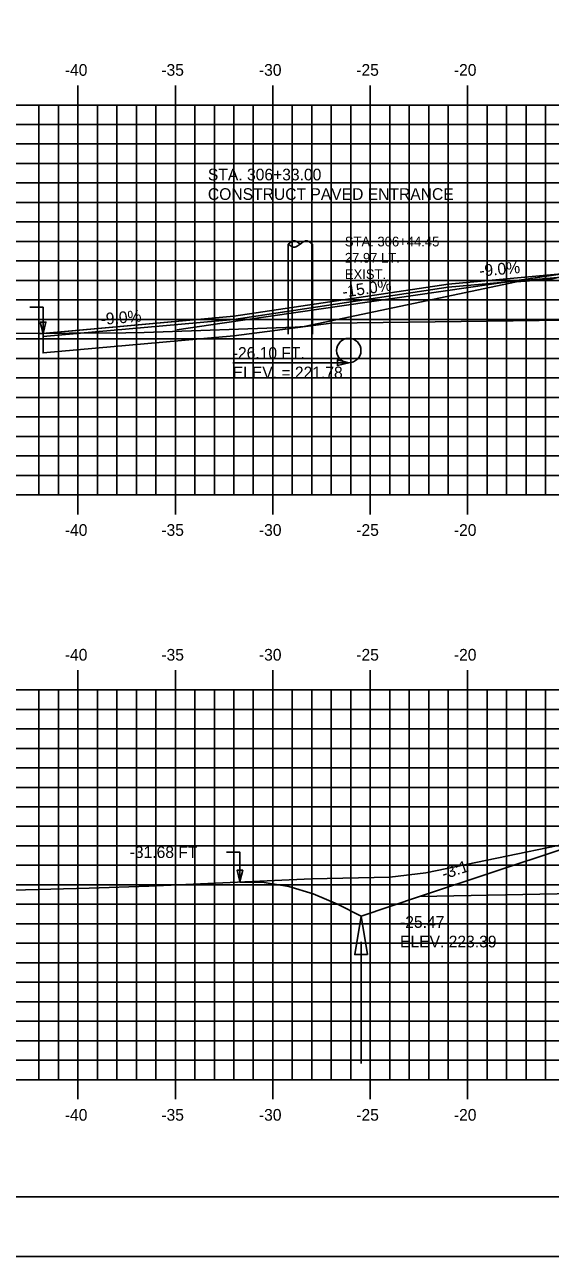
# Model space of a CAD drawing. Extents: x 1137433 to 1137603, y 608981 to 609091.
# Drawn here: x 1137472.9 to 1137499.9, y 608981.3 to 609044.5 of the extents above; entities that cross this region are included whole.
import ezdxf

# ---------------------------------------------------------------- set-up
doc = ezdxf.new("R2010")
doc.units = 0
for name, color, linetype in [('ANNOTATION', 7, 'Continuous'), ('BORDER', 7, 'Continuous'), ('D_Drainage_Culvert', 7, 'Continuous'), ('D_Drainage_Ditch_Line', 7, 'Continuous'), ('D_Roadway_Edge_Shoulder', 7, 'Continuous'), ('D_Roadway_SlopeLines', 7, 'Continuous'), ('D_Roadway_SubGrade', 7, 'Continuous'), ('D_Text_Monospaced', 7, 'Continuous'), ('D_Text_Standard', 7, 'Continuous'), ('H_V ANNOTATION', 7, 'Continuous'), ('MAJOR', 7, 'Continuous'), ('MINOR', 7, 'Continuous'), ('PATTERNING', 7, 'Continuous'), ('PLOT BOUNDARY', 7, 'Continuous'), ('S_Roadway_Centerline', 7, 'Continuous'), ('S_Utilities_Pole_Power', 7, 'Continuous')]:
    doc.layers.add(name, color=color, linetype=linetype)

msp = doc.modelspace()

# ---------------------------------------------------------------- linework, layer by layer
for points in [[(1137480.733, 609028.805), (1137483.056, 609029.142), (1137500.653, 609031.693), (1137501.13, 609031.716), (1137504.653, 609031.88), (1137505.953, 609031.941), (1137515.653, 609032.393), (1137516.953, 609032.453), (1137526.653, 609032.905), (1137527.13, 609032.89), (1137530.653, 609032.772), (1137537.514, 609030.485), (1137538.461, 609030.169)], [(1137483.968, 609000.475), (1137485.218, 609000.445), (1137486.468, 609000.245), (1137487.718, 608999.875), (1137488.968, 608999.335), (1137490.184, 608998.727), (1137493.184, 608999.727), (1137500.652, 609002.217), (1137500.653, 609002.217), (1137504.653, 609002.457), (1137515.653, 609003.117), (1137526.653, 609003.777), (1137530.966, 609003.69), (1137533.053, 609003.002), (1137534.745, 609002.444), (1137536.143, 609001.984), (1137537.258, 609001.616), (1137538.984, 609001.048)]]:
    msp.add_lwpolyline(points)
at = {"layer": 'BORDER'}
msp.add_lwpolyline([(1137440.653, 608984.335), (1137600.653, 608984.335), (1137600.653, 609089.335), (1137440.653, 609089.335)], close=True, dxfattribs=at)
at = {"layer": 'D_Drainage_Culvert'}
msp.add_circle((1137489.553, 609027.74), 0.625, dxfattribs=at)
at = {"layer": 'D_Drainage_Ditch_Line'}
msp.add_line((1137490.184, 608997.415), (1137490.183, 608991.171), dxfattribs=at)
msp.add_lwpolyline([(1137490.512, 608996.759), (1137489.856, 608996.759), (1137490.184, 608998.727)], close=True, dxfattribs=at)
at = {"layer": 'D_Roadway_Edge_Shoulder'}
msp.add_lwpolyline([(1137473.862, 609028.455), (1137483.653, 609029.337), (1137494.653, 609030.987), (1137500.653, 609031.527)], dxfattribs=at)
at = {"layer": 'D_Roadway_SlopeLines'}
for points in [[(1137490.184, 608998.727), (1137488.968, 608999.335), (1137487.718, 608999.875), (1137486.468, 609000.245), (1137485.218, 609000.445), (1137483.968, 609000.475)], [(1137493.184, 608999.727), (1137490.184, 608998.727)]]:
    msp.add_lwpolyline(points, dxfattribs=at)
at = {"layer": 'D_Roadway_SubGrade'}
for p, q in [((1137500.653, 609031.693), (1137494.653, 609031.153)), ((1137483.653, 609029.503), (1137494.653, 609031.153)), ((1137483.653, 609029.503), (1137473.862, 609028.622)), ((1137488.653, 609029.141), (1137500.653, 609029.3)), ((1137488.653, 609029.141), (1137500.653, 609029.3)), ((1137473.862, 609028.622), (1137473.862, 609028.455))]:
    msp.add_line(p, q, dxfattribs=at)
msp.add_lwpolyline([(1137473.862, 609028.622), (1137473.862, 609027.622), (1137483.653, 609028.503), (1137488.653, 609029.141)], dxfattribs=at)
msp.add_lwpolyline([(1137504.653, 609002.04), (1137504.653, 609002.207), (1137500.653, 609001.967), (1137500.653, 609002.217), (1137500.652, 609002.217), (1137493.184, 608999.727), (1137504.653, 608999.957)], close=True, dxfattribs=at)
at = {"layer": 'D_Text_Standard'}
msp.add_line((1137483.598, 609027.115), (1137487.98, 609027.115), dxfattribs=at)
for points in [[(1137473.862, 609028.622), (1137473.86, 609029.96), (1137473.18, 609029.96)], [(1137489.553, 609027.115), (1137488.66, 609027.115), (1137487.98, 609027.115)], [(1137483.97, 609000.502), (1137483.961, 609002.011), (1137483.281, 609002.011)]]:
    msp.add_lwpolyline(points, dxfattribs=at)
for points in [[(1137473.862, 609028.622), (1137473.716, 609029.204), (1137474.007, 609029.204)], [(1137489.553, 609027.115), (1137488.971, 609026.97), (1137488.971, 609027.261)], [(1137483.97, 609000.502), (1137483.821, 609001.083), (1137484.112, 609001.085)]]:
    msp.add_lwpolyline(points, close=True, dxfattribs=at)
at = {"layer": 'MAJOR'}
for p, q in [((1137475.653, 609041.337), (1137475.653, 609040.335)), ((1137480.653, 609041.337), (1137480.653, 609040.335)), ((1137485.653, 609041.337), (1137485.653, 609040.335)), ((1137490.653, 609041.337), (1137490.653, 609040.335)), ((1137495.653, 609041.337), (1137495.653, 609040.335)), ((1137445.653, 609040.335), (1137585.653, 609040.335)), ((1137445.653, 609040.335), (1137585.653, 609040.335)), ((1137475.653, 609020.335), (1137475.653, 609040.335)), ((1137480.653, 609020.335), (1137480.653, 609040.335)), ((1137485.653, 609020.335), (1137485.653, 609040.335)), ((1137490.653, 609020.335), (1137490.653, 609040.335)), ((1137495.653, 609020.335), (1137495.653, 609040.335)), ((1137445.653, 609035.335), (1137585.653, 609035.335)), ((1137445.653, 609030.335), (1137585.653, 609030.335)), ((1137445.653, 609025.335), (1137585.653, 609025.335)), ((1137445.653, 609020.335), (1137585.653, 609020.335)), ((1137445.653, 609020.335), (1137585.653, 609020.335)), ((1137475.653, 609019.333), (1137475.653, 609020.335)), ((1137480.653, 609019.333), (1137480.653, 609020.335)), ((1137485.653, 609019.333), (1137485.653, 609020.335)), ((1137490.653, 609019.333), (1137490.653, 609020.335)), ((1137495.653, 609019.333), (1137495.653, 609020.335)), ((1137475.653, 609011.337), (1137475.653, 609010.335)), ((1137480.653, 609011.337), (1137480.653, 609010.335)), ((1137485.653, 609011.337), (1137485.653, 609010.335)), ((1137490.653, 609011.337), (1137490.653, 609010.335)), ((1137495.653, 609011.337), (1137495.653, 609010.335)), ((1137445.653, 609010.335), (1137585.653, 609010.335)), ((1137445.653, 609010.335), (1137585.653, 609010.335)), ((1137475.653, 608990.335), (1137475.653, 609010.335)), ((1137480.653, 608990.335), (1137480.653, 609010.335)), ((1137485.653, 608990.335), (1137485.653, 609010.335)), ((1137490.653, 608990.335), (1137490.653, 609010.335)), ((1137495.653, 608990.335), (1137495.653, 609010.335)), ((1137445.653, 609005.335), (1137585.653, 609005.335)), ((1137445.653, 609000.335), (1137585.653, 609000.335)), ((1137445.653, 608995.335), (1137585.653, 608995.335)), ((1137445.653, 608990.335), (1137585.653, 608990.335)), ((1137445.653, 608990.335), (1137585.653, 608990.335)), ((1137475.653, 608989.333), (1137475.653, 608990.335)), ((1137480.653, 608989.333), (1137480.653, 608990.335)), ((1137485.653, 608989.333), (1137485.653, 608990.335)), ((1137490.653, 608989.333), (1137490.653, 608990.335)), ((1137495.653, 608989.333), (1137495.653, 608990.335))]:
    msp.add_line(p, q, dxfattribs=at)
at = {"layer": 'MINOR'}
for p, q in [((1137473.653, 609020.335), (1137473.653, 609040.335)), ((1137474.653, 609020.335), (1137474.653, 609040.335)), ((1137476.653, 609020.335), (1137476.653, 609040.335)), ((1137477.653, 609020.335), (1137477.653, 609040.335)), ((1137478.653, 609020.335), (1137478.653, 609040.335)), ((1137479.653, 609020.335), (1137479.653, 609040.335)), ((1137481.653, 609020.335), (1137481.653, 609040.335)), ((1137482.653, 609020.335), (1137482.653, 609040.335)), ((1137483.653, 609020.335), (1137483.653, 609040.335)), ((1137484.653, 609020.335), (1137484.653, 609040.335)), ((1137486.653, 609020.335), (1137486.653, 609040.335)), ((1137487.653, 609020.335), (1137487.653, 609040.335)), ((1137488.653, 609020.335), (1137488.653, 609040.335)), ((1137489.653, 609020.335), (1137489.653, 609040.335)), ((1137491.653, 609020.335), (1137491.653, 609040.335)), ((1137492.653, 609020.335), (1137492.653, 609040.335)), ((1137493.653, 609020.335), (1137493.653, 609040.335)), ((1137494.653, 609020.335), (1137494.653, 609040.335)), ((1137496.653, 609020.335), (1137496.653, 609040.335)), ((1137497.653, 609020.335), (1137497.653, 609040.335)), ((1137498.653, 609020.335), (1137498.653, 609040.335)), ((1137499.653, 609020.335), (1137499.653, 609040.335)), ((1137445.653, 609039.335), (1137585.653, 609039.335)), ((1137445.653, 609038.335), (1137585.653, 609038.335)), ((1137445.653, 609037.335), (1137585.653, 609037.335)), ((1137445.653, 609036.335), (1137585.653, 609036.335)), ((1137445.653, 609034.335), (1137585.653, 609034.335)), ((1137445.653, 609033.335), (1137585.653, 609033.335)), ((1137445.653, 609032.335), (1137585.653, 609032.335)), ((1137445.653, 609031.335), (1137585.653, 609031.335)), ((1137445.653, 609029.335), (1137585.653, 609029.335)), ((1137445.653, 609028.335), (1137585.653, 609028.335)), ((1137445.653, 609027.335), (1137585.653, 609027.335)), ((1137445.653, 609026.335), (1137585.653, 609026.335)), ((1137445.653, 609024.335), (1137585.653, 609024.335)), ((1137445.653, 609023.335), (1137585.653, 609023.335)), ((1137445.653, 609022.335), (1137585.653, 609022.335)), ((1137445.653, 609021.335), (1137585.653, 609021.335)), ((1137473.653, 608990.335), (1137473.653, 609010.335)), ((1137474.653, 608990.335), (1137474.653, 609010.335)), ((1137476.653, 608990.335), (1137476.653, 609010.335)), ((1137477.653, 608990.335), (1137477.653, 609010.335)), ((1137478.653, 608990.335), (1137478.653, 609010.335)), ((1137479.653, 608990.335), (1137479.653, 609010.335)), ((1137481.653, 608990.335), (1137481.653, 609010.335)), ((1137482.653, 608990.335), (1137482.653, 609010.335)), ((1137483.653, 608990.335), (1137483.653, 609010.335)), ((1137484.653, 608990.335), (1137484.653, 609010.335)), ((1137486.653, 608990.335), (1137486.653, 609010.335)), ((1137487.653, 608990.335), (1137487.653, 609010.335)), ((1137488.653, 608990.335), (1137488.653, 609010.335)), ((1137489.653, 608990.335), (1137489.653, 609010.335)), ((1137491.653, 608990.335), (1137491.653, 609010.335)), ((1137492.653, 608990.335), (1137492.653, 609010.335)), ((1137493.653, 608990.335), (1137493.653, 609010.335)), ((1137494.653, 608990.335), (1137494.653, 609010.335)), ((1137496.653, 608990.335), (1137496.653, 609010.335)), ((1137497.653, 608990.335), (1137497.653, 609010.335)), ((1137498.653, 608990.335), (1137498.653, 609010.335)), ((1137499.653, 608990.335), (1137499.653, 609010.335)), ((1137445.653, 609009.335), (1137585.653, 609009.335)), ((1137445.653, 609008.335), (1137585.653, 609008.335)), ((1137445.653, 609007.335), (1137585.653, 609007.335)), ((1137445.653, 609006.335), (1137585.653, 609006.335)), ((1137445.653, 609004.335), (1137585.653, 609004.335)), ((1137445.653, 609003.335), (1137585.653, 609003.335)), ((1137445.653, 609002.335), (1137585.653, 609002.335)), ((1137445.653, 609001.335), (1137585.653, 609001.335)), ((1137445.653, 608999.335), (1137585.653, 608999.335)), ((1137445.653, 608998.335), (1137585.653, 608998.335)), ((1137445.653, 608997.335), (1137585.653, 608997.335)), ((1137445.653, 608996.335), (1137585.653, 608996.335)), ((1137445.653, 608994.335), (1137585.653, 608994.335)), ((1137445.653, 608993.335), (1137585.653, 608993.335)), ((1137445.653, 608992.335), (1137585.653, 608992.335)), ((1137445.653, 608991.335), (1137585.653, 608991.335))]:
    msp.add_line(p, q, dxfattribs=at)
at = {"layer": 'PATTERNING'}
msp.add_line((1137483.653, 609029.503), (1137473.653, 609028.603), dxfattribs=at)
at = {"layer": 'PLOT BOUNDARY'}
msp.add_lwpolyline([(1137432.56, 608981.276), (1137602.56, 608981.276), (1137602.56, 609091.276), (1137432.56, 609091.276)], close=True, dxfattribs=at)
at = {"layer": 'S_Roadway_Centerline'}
for points in [[(1137445.653, 609028.703), (1137460.066, 609028.556), (1137460.633, 609028.548), (1137478.111, 609028.646), (1137479.06, 609028.67), (1137486.804, 609028.946), (1137487.264, 609028.966), (1137498.159, 609031.27), (1137499.941, 609031.407), (1137500.381, 609031.497), (1137500.618, 609031.505), (1137510.823, 609031.631), (1137513.506, 609031.615), (1137521.857, 609031.577), (1137522.115, 609031.498), (1137522.315, 609031.418), (1137525.004, 609031.182), (1137525.888, 609031.035), (1137530.343, 609030.697), (1137531.057, 609030.727), (1137534.993, 609030.582), (1137537.95, 609030.665), (1137547.085, 609030.758)], [(1137445.653, 609000.068), (1137449.602, 608999.97), (1137450.522, 608999.958), (1137471.63, 609000.04), (1137476.229, 609000.162), (1137479.292, 609000.271), (1137487.646, 609000.636), (1137491.658, 609000.725), (1137493.508, 609000.954), (1137500.799, 609002.457), (1137507.803, 609002.706), (1137511.492, 609002.758), (1137515.564, 609002.741), (1137522.315, 609002.7), (1137524.764, 609002.536), (1137526.981, 609002.445), (1137539.217, 609001.937)]]:
    msp.add_lwpolyline(points, dxfattribs=at)
at = {"layer": 'S_Utilities_Pole_Power'}
for p, q in [((1137486.435, 609033.203), (1137486.591, 609033.314)), ((1137486.435, 609028.584), (1137486.438, 609033.203)), ((1137486.591, 609033.092), (1137486.435, 609033.203)), ((1137486.903, 609033.314), (1137487.06, 609033.203)), ((1137487.06, 609033.203), (1137486.903, 609033.092)), ((1137487.216, 609033.314), (1137487.06, 609033.203)), ((1137487.685, 609033.203), (1137487.529, 609033.314)), ((1137487.685, 609028.584), (1137487.688, 609033.203))]:
    msp.add_line(p, q, dxfattribs=at)
for centre, start, end in [((1137486.747, 609033.093), 90, 125.26439), ((1137486.747, 609033.314), 234.73561, 270), ((1137486.747, 609033.093), 54.73561, 90), ((1137486.747, 609033.314), 270, 305.26439), ((1137487.372, 609033.093), 90, 125.26439), ((1137487.372, 609033.093), 54.73561, 90)]:
    msp.add_arc(centre, 0.271, start, end, dxfattribs=at)

# ---------------------------------------------------------------- texts
at = {"layer": 'ANNOTATION'}
for s, p in [('STA. 306+33.00', (1137482.323, 609036.469)), ('CONSTRUCT PAVED ENTRANCE', (1137482.323, 609035.467))]:
    msp.add_text(s, height=0.6, dxfattribs=at).set_placement(p)
for s, rotation, p in [('-9.0%', 5.05846, (1137496.277, 609031.535)), ('-15.0%', 8.25039, (1137489.263, 609030.452)), ('-9.0%', 5.05846, (1137476.846, 609029.046)), ('-3:1', 18.43483, (1137494.435, 609000.598))]:
    msp.add_text(s, height=0.6, rotation=rotation, dxfattribs=at).set_placement(p)
at = {"layer": 'D_Text_Monospaced'}
for s, height, p in [('STA. 306+44.45', 0.49998, (1137489.351, 609033.082)), ('27.97 LT.', 0.5, (1137489.351, 609032.248)), ('EXIST. ', 0.5, (1137489.351, 609031.408))]:
    msp.add_text(s, height=height, dxfattribs=at).set_placement(p)
at = {"layer": 'D_Text_Standard'}
for s, p in [('-26.10 FT.', (1137483.598, 609027.315)), ('ELEV. = 221.78', (1137483.598, 609026.315)), ('-31.68 FT', (1137478.308, 609001.711)), ('-25.47', (1137492.184, 608998.127)), ('ELEV. 223.39', (1137492.184, 608997.125))]:
    msp.add_text(s, height=0.6, dxfattribs=at).set_placement(p)
at = {"layer": 'H_V ANNOTATION'}
for s, p in [('-40', (1137474.979, 609041.835)), ('-35', (1137479.933, 609041.835)), ('-30', (1137484.941, 609041.835)), ('-25', (1137489.938, 609041.835)), ('-20', (1137494.946, 609041.835)), ('-40', (1137474.979, 609018.235)), ('-35', (1137479.933, 609018.235)), ('-30', (1137484.941, 609018.235)), ('-25', (1137489.938, 609018.235)), ('-20', (1137494.946, 609018.235)), ('-40', (1137474.979, 609011.835)), ('-35', (1137479.933, 609011.835)), ('-30', (1137484.941, 609011.835)), ('-25', (1137489.938, 609011.835)), ('-20', (1137494.946, 609011.835)), ('-40', (1137474.979, 608988.235)), ('-35', (1137479.933, 608988.235)), ('-30', (1137484.941, 608988.235)), ('-25', (1137489.938, 608988.235)), ('-20', (1137494.946, 608988.235))]:
    msp.add_text(s, height=0.6, dxfattribs=at).set_placement(p)

doc.saveas('drawing.dxf')
